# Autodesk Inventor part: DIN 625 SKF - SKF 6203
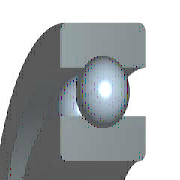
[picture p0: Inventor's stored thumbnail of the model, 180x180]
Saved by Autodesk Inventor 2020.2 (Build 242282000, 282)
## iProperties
Manager: www.cadconsulting.pl
Company: Fabian Stasiak CAD Consulting
Created: 2010-02
Part Number: DIN 625 SKF - SKF 6203
Material: Stal, miękka
Description: Łożyska kulkowe jednorzędowe
Document SubType Name: Modeling
Standard: DIN 625
Designer: F.Stasiak
Standards Organization: DIN
Language: pl-PL
Size Designation: SKF 6203
Categories: <MemberInstance><Categories><Category DisplayName="Części wałów" InternalName="7f7aeb1f-a693-4053-b835-cee3144e0d98" Mnemonic="SHFT"><Category DisplayName="Łoży
Density: 7.86 g/cm^3
Appearance: Metal-Stal
IsCustomPart: 0
Author: F.Stasiak
Subject: Zbiór ćwiczeń. Autodesk Inventor 2020. Kurs podstawowy
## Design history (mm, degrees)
node "Sketch1"
node "WorkPoint1"
sketch "Sketch2"
  geometry: L1 (8.5, 12)-(20, 12); L2 (8.5, 0)-(8.5, 12); L3 (20, 0)-(8.5, 0); L4 (20, 12)-(20, 0); L5 (0, 0)-(0, 20); L6 (0, 0)-(0, 20); L7 (-7.2, 0)-(43.2, 0) reference
  constraints: 12 end point, 3 vertical, 2 horizontal, 1 collinear, 1 other
  dimensions: "d1" = 17 diameter of L1.start L5 (= Diam); "d3" = 40 diameter of L1.end L5 (= DD); "d5" = 12 distance of L2.start L1.start (= msp_mdtd2)
revolve "Revolution1" sketch "Sketch2" stored, may be unused: angle "d6" = 360 deg
node "WorkAxis1"
node "WorkPlane3"
sketch "Sketch3"
  geometry: L1 (16.32, 12)-(16.32, 8.76); L2 (12.18, 12)-(16.32, 12); L3 (12.18, 8.76)-(12.18, 12); L4 (12.18, 0)-(12.18, 3.24); L5 (16.32, 0)-(12.18, 0); L6 (16.32, 3.24)-(16.32, 0); L7 (20, 0)-(-20, 0) reference; L8 (20, 12)-(-20, 12) reference; L9 (0, -42.29)-(0, 61.29); L10 (0, 82.007)-(0, -63.007) reference; A1 r 3.45 centre (14.25, 6) between (16.32, 3.24) and (16.32, 8.76); A2 r 3.45 centre (14.25, 6) between (12.18, 8.76) and (12.18, 3.24)
  constraints: 14 end point, 4 collinear, 4 point on circle, 4 vertical, 2 centre point, 2 concentric, 2 horizontal, 2 point on line
  dimensions: "d9" = 6.9 diameter of A1 (= msp_mdtd6); "d21" = 12.18 distance between parallel lines of L9 L4 (= 0.5 x msp_d1); "d22" = 14.25 distance from line of L9 A1.centre (= 0.5 x msp_ds); "d23" = 16.32 distance between parallel lines of L9 L6 (= 0.5 x msp_dd1)
revolve "Revolution2" sketch "Sketch3" stored, may be unused: angle "d10" = 360 deg
node "WorkPlane4"
node "Sketch4"
node "WorkPoint2"
revolve "Revolution3" stored, may be unused: angle "d16" = 360 deg
pattern_circular "PolarArray1" dims "d17" = 65.95652 (= msp_pocet), angle "d19" = 360 deg
fillet "Fillet1" dims "d20" = 0.6 (= r)
body "Solid1"
sketch "Sketch5"
  geometry: L1 (14.25, 2.55)-(14.25, 9.45); L2 (16.32, 0)-(-16.32, 0) reference; L3 (14.25, 2.55)-(14.25, 9.45); A1 r 3.45 centre (14.25, 6) between (14.25, 2.55) and (14.25, 9.45); A2 r 3.45 centre (14.25, 6) between (16.32, 3.24) and (16.32, 8.76) reference
  constraints: 4 end point, 2 point on circle, 1 centre point, 1 concentric, 1 vertical
  dimensions: "d13" = 0 horizontal distance of A1.centre L1.start; "d15" = 6.9001 diameter of A1 (computed from msp_mdtd6)
other parameters: "Diam" = 17 [user parameter; used in 3 equation terms], "DD" = 40 [user parameter; used in 3 equation terms], "B" = 12 [user parameter; used in 1 equation term], "r" = 0.6 [user parameter; used in 1 equation term], "msp_ds" = 28.5 (= 0.5 x Diam + 0.5 x DD) [user parameter; used in 5 equation terms], "msp_d0" = 6.9 (= -0.3 x Diam + 0.3 x DD) [user parameter; used in 4 equation terms], "msp_d1" = 24.36 (= msp_ds - 0.6 x msp_d0) [user parameter; used in 1 equation term], "msp_dd1" = 32.64 (= msp_ds + 0.6 x msp_d0) [user parameter; used in 1 equation term], "msp_pom" = 42.75 (= 1.5 x msp_ds) [user parameter; used in 1 equation term], "msp_mdtd2" = 12 (= B) [user parameter; used in 3 equation terms], "msp_mdtd4" = 28.5 (= msp_ds) [user parameter], "msp_mdtd6" = 6.9 (= msp_d0) [user parameter; used in 2 equation terms], "msp_mdtd7" = 6 (= 0.5 x msp_mdtd2) [user parameter], "msp_pocet" = 65.95652 (computed from msp_d0, msp_pom) [user parameter; used in 1 equation term], "d2" = 72 (derived), "d4" = 19 (derived), "d7" = 0, "d8" = 15.6 (derived), "d11" = -12 (computed from msp_mdtd2), "d12" = 0 (derived), "d14" = 15.6001 (derived), "d26" = 0, "d27" = 0, "d28" = 0, "d29" = 0, "d30" = 0
